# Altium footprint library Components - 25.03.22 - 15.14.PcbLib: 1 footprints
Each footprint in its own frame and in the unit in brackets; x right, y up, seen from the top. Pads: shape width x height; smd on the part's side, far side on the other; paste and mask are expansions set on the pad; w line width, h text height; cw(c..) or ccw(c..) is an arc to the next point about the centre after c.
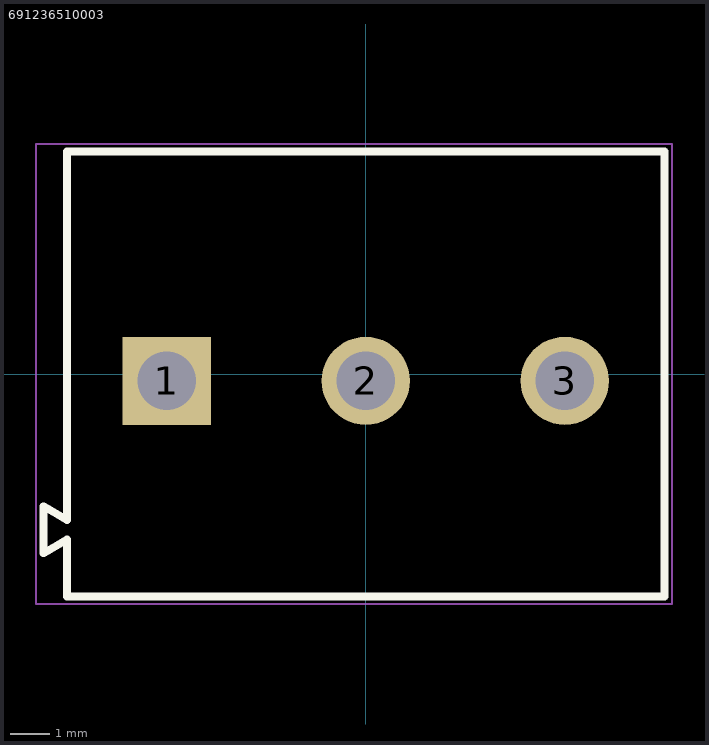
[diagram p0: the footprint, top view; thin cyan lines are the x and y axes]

## 691236510003 [mm] "Horizontal Cable Entry with Rising Cage Clamp, pitch 5.08mm, 03p"
height 18
pads (3):
  rect 2.25x2.25 hole 1.5: 1(-5.08,-0.175)
  round 2.25 hole 1.5: 2(0,-0.175) 3(5.08,-0.175)
Top Overlay:
  lines w0.2: -7.621,-4.223 -8.22,-4.575 -8.22,-3.375 -7.621,-3.727 ; -7.62,-4.225 -7.62,-5.675 7.62,-5.675 7.62,5.675 -7.62,5.675 -7.62,-3.726
M13 Assembly Top:
  lines w0.1: -7.621,-4.223 -8.22,-4.575 -8.22,-3.375 -7.621,-3.727 ; -7.62,-4.225 -7.62,-5.675 7.62,-5.675 7.62,5.675 -7.62,5.675 -7.62,-3.726
M15 Courtyard Top:
  lines w0.05: -0.5,0 0.5,0 ; 0,-0.5 0,0.5 ; -8.42,-5.875 7.82,-5.875 7.82,5.875 -8.42,5.875 -8.42,-5.875
3D body "691236510003.stp": height 18.1, standoff -3.9, extent -8.22,-5.675 7.62,5.675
